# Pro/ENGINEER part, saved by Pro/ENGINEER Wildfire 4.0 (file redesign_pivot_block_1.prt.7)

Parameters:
  METRIC = "NO"

Other parameters: PITCH, DRILL_POINT_ANGLE, DRILL_DEPTH, DRILL_DIAMETER, THREAD_DIAMETER, THREADS_PER_INCH, THREAD_DEPTH, THREAD_LENGTH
